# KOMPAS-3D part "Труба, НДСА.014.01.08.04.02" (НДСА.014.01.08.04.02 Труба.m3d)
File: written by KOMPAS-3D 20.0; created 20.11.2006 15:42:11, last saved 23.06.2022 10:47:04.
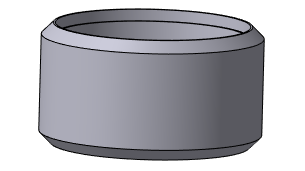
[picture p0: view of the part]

Document properties: Автор: Устинов А.В.; Организация: ЭСТО-Вакуум; Полное имя файла: C:\Users\cherbakova\Desktop\PLM\НДСА.014.01.08.04.02 Труба.m3d

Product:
- Part/product: Труба  | designation НДСА.014.01.08.04.02
    Материал: Труба$d114х8 ГОСТ 8732-78;20 ГОСТ 8731-74$ (density 7859 kg/m3)
    Масса: 1.17099
    additional columns: <item xmlns="http://appius.ru/pdm" xmlns:xs="http://www.w3.org/2001/XMLSchema" x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; <item xmlns="http://appius.ru/pdm" xmlns:xs="http://www.w3.org/2001/XMLSchema" x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; <item xmlns="http://appius.ru/pdm" xmlns:xs="http://www.w3.org/2001/XMLSchema" x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; <item xmlns="http://appius.ru/pdm" xmlns:xs="http://www.w3.org/2001/XMLSchema" x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; <item xmlns="http://appius.ru/pdm" xmlns:xs="http://www.w3.org/2001/XMLSchema" x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; <item xmlns="http://appius.ru/pdm" xmlns:xs="http://www.w3.org/2001/XMLSchema" x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
    source file: НДСА.014.01.08.04.02 Труба.CDW

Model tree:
1. Плоскость XY
2. Плоскость ZX
3. Плоскость ZY
4. Начало координат
5. Эскиз:1
6. Операция вращения:1  (labels: Труба$d114х8 ГОСТ 8732-78;20 ГОСТ 8731-74$)
     Угол 1 = 360

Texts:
  НДСА.014.01.08.04.02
